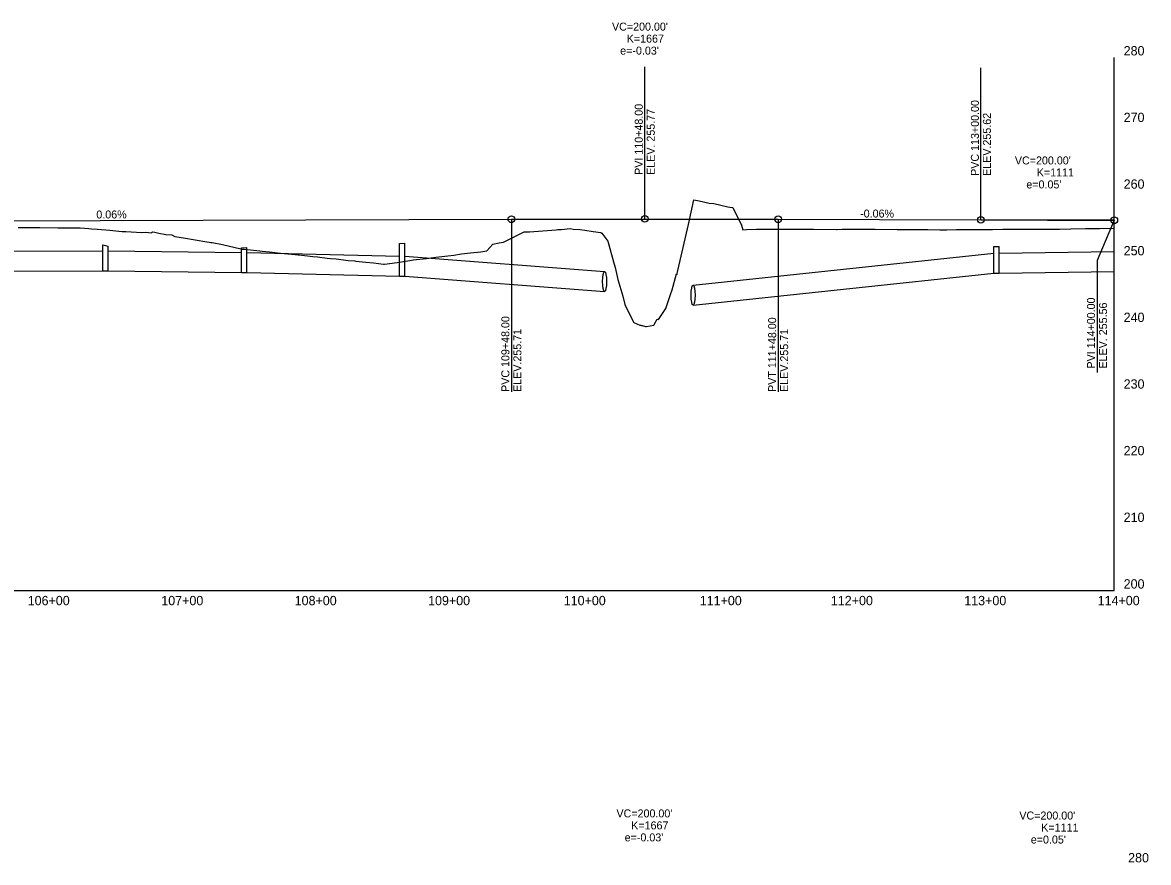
# Model space of a CAD drawing. Extents: x 1930770 to 1938778, y 596900 to 600561.
# Drawn here: x 1932838 to 1933682, y 599461 to 600091 of the extents above; entities that cross this region are included whole.
import ezdxf

# ---------------------------------------------------------------- set-up
doc = ezdxf.new("R2010")
doc.units = 0
for name, color, linetype in [('S_CROSS_DRAIN_ANNOT', 7, 'Continuous'), ('S_DROP_INLET_ANNOT', 7, 'Continuous'), ('S_ELECTRIC_UTILITIES_ANNOT', 7, 'Continuous'), ('S_HIST_HIGH_WATER_ANNOT', 7, 'Continuous'), ('S_SIGN_ANNOT', 7, 'Continuous'), ('S_WATER_UTILITIES_ANNOT', 7, 'Continuous')]:
    doc.layers.add(name, color=color, linetype=linetype)

msp = doc.modelspace()

# ---------------------------------------------------------------- linework, layer by layer
at = {"layer": 'S_CROSS_DRAIN_ANNOT'}
for p, q in [((1933656.02, 599664.63), (1933656.02, 600064.63)), ((1932156.02, 599664.63), (1933656.02, 599664.63))]:
    msp.add_line(p, q, dxfattribs=at)
at = {"layer": 'S_ELECTRIC_UTILITIES_ANNOT'}
for p, q in [((1933304.02, 599973.5), (1933304.02, 600057.5)), ((1933556.02, 599972.75), (1933556.02, 600056.75)), ((1933304.02, 599943.5), (1933304.02, 599973.5)), ((1933556.02, 599942.75), (1933556.02, 599972.75)), ((1933204.02, 599943.2), (1933204.02, 599913.2)), ((1933254.02, 599943.35), (1933304.02, 599943.5)), ((1933304.02, 599943.5), (1933354.02, 599943.35)), ((1933404.02, 599943.2), (1933404.02, 599913.2)), ((1933606.02, 599942.6), (1933656.02, 599942.45)), ((1933656.02, 599942.45), (1933643.04, 599912.19)), ((1933656.02, 599942.45), (1933656.02, 599942.45)), ((1933204.02, 599913.2), (1933204.02, 599813.65)), ((1933404.02, 599913.2), (1933404.02, 599813.65)), ((1933643.04, 599912.19), (1933643.04, 599828.19))]:
    msp.add_line(p, q, dxfattribs=at)
for centre in [(1933204.02, 599943.2), (1933304.02, 599943.5), (1933404.02, 599943.2), (1933556.02, 599942.75), (1933656.02, 599942.45)]:
    msp.add_circle(centre, 2.5, dxfattribs=at)
at = {"layer": 'S_HIST_HIGH_WATER_ANNOT'}
for p, q in [((1932606.02, 599941.41), (1933204.02, 599943.2)), ((1933404.02, 599943.2), (1933556.02, 599942.75))]:
    msp.add_line(p, q, dxfattribs=at)
for points in [[(1933204.02, 599943.2), (1933208.19, 599943.21), (1933212.36, 599943.23), (1933216.52, 599943.24), (1933220.69, 599943.25), (1933224.86, 599943.26), (1933229.02, 599943.27), (1933233.19, 599943.28), (1933237.36, 599943.29), (1933241.52, 599943.29), (1933245.69, 599943.3), (1933249.86, 599943.31), (1933254.02, 599943.32), (1933258.19, 599943.32), (1933262.36, 599943.33), (1933266.52, 599943.33), (1933270.69, 599943.34), (1933274.86, 599943.34), (1933279.02, 599943.34), (1933283.19, 599943.35), (1933287.36, 599943.35), (1933291.52, 599943.35), (1933295.69, 599943.35), (1933299.86, 599943.35), (1933308.19, 599943.35), (1933312.36, 599943.35), (1933316.52, 599943.35), (1933320.69, 599943.35), (1933324.86, 599943.35), (1933329.02, 599943.34), (1933333.19, 599943.34), (1933337.36, 599943.34), (1933341.52, 599943.33), (1933345.69, 599943.33), (1933349.86, 599943.32), (1933354.02, 599943.32), (1933358.19, 599943.31), (1933362.36, 599943.3), (1933366.52, 599943.29), (1933370.69, 599943.29), (1933374.86, 599943.28), (1933379.02, 599943.27), (1933383.19, 599943.26), (1933387.36, 599943.25), (1933391.52, 599943.24), (1933395.69, 599943.23), (1933399.86, 599943.21), (1933404.02, 599943.2)], [(1933556.02, 599942.75), (1933560.19, 599942.73), (1933564.36, 599942.72), (1933568.52, 599942.71), (1933572.69, 599942.7), (1933576.86, 599942.69), (1933581.02, 599942.69), (1933585.19, 599942.68), (1933589.36, 599942.67), (1933593.52, 599942.67), (1933597.69, 599942.66), (1933601.86, 599942.66), (1933606.02, 599942.65), (1933610.19, 599942.65), (1933614.36, 599942.65), (1933618.52, 599942.65), (1933622.69, 599942.65), (1933626.86, 599942.65), (1933631.02, 599942.65), (1933635.19, 599942.65), (1933639.36, 599942.65), (1933643.52, 599942.66), (1933647.69, 599942.66), (1933651.86, 599942.67), (1933656.02, 599942.67)]]:
    msp.add_lwpolyline(points, dxfattribs=at)
at = {"layer": 'S_SIGN_ANNOT'}
for p, q in [((1932897.73, 599904.58), (1932897.73, 599924.05)), ((1932897.73, 599924.05), (1932901.73, 599923.09)), ((1932901.73, 599904.58), (1932901.73, 599923.09)), ((1933001.63, 599921.87), (1933005.63, 599921.91)), ((1933001.63, 599903.23), (1933001.63, 599921.87)), ((1933005.63, 599903.23), (1933005.63, 599921.91)), ((1933120.14, 599924.93), (1933124.14, 599925.24)), ((1933120.14, 599900.43), (1933120.14, 599924.93)), ((1933124.14, 599900.43), (1933124.14, 599925.24)), ((1933565.71, 599902.73), (1933565.71, 599922.86)), ((1933565.71, 599922.86), (1933569.71, 599922.83)), ((1933569.71, 599902.73), (1933569.71, 599922.83)), ((1932819.18, 599919.33), (1932897.73, 599919.58)), ((1932901.73, 599919.58), (1933001.63, 599918.23)), ((1933005.63, 599918.23), (1933120.14, 599915.43)), ((1933124.14, 599915.43), (1933273.9, 599903.98)), ((1933340.26, 599893.78), (1933565.71, 599917.73)), ((1933569.71, 599917.73), (1933656.02, 599918.98)), ((1932819.18, 599904.33), (1932897.73, 599904.58)), ((1932897.73, 599904.58), (1932901.73, 599904.58)), ((1932901.73, 599904.58), (1933001.63, 599903.23)), ((1933001.63, 599903.23), (1933005.63, 599903.23)), ((1933005.63, 599903.23), (1933120.14, 599900.43)), ((1933569.71, 599902.73), (1933656.02, 599903.98)), ((1933120.14, 599900.43), (1933124.14, 599900.43)), ((1933124.14, 599900.43), (1933273.9, 599888.98)), ((1933340.26, 599878.78), (1933565.71, 599902.73)), ((1933565.71, 599902.73), (1933569.71, 599902.73))]:
    msp.add_line(p, q, dxfattribs=at)
for centre in [(1933273.9, 599896.48), (1933340.26, 599886.28)]:
    msp.add_ellipse(centre, major_axis=(0, 7.5), ratio=0.2, dxfattribs=at)
at = {"layer": 'S_WATER_UTILITIES_ANNOT'}
msp.add_lwpolyline([(1932834.28, 599937.02), (1932843.89, 599936.98), (1932850.52, 599936.93), (1932863.99, 599936.81), (1932867.66, 599936.8), (1932872.05, 599936.77), (1932880.8, 599936.73), (1932887.28, 599936.22), (1932889.22, 599936.06), (1932893.59, 599935.7), (1932893.86, 599935.68), (1932903.14, 599934.91), (1932909.83, 599934.32), (1932912.23, 599934.09), (1932915.12, 599933.95), (1932926.9, 599933.35), (1932929.71, 599933.61), (1932934.33, 599932.95), (1932935.11, 599933.75), (1932936.66, 599933.42), (1932939.78, 599932.74), (1932945.12, 599931.65), (1932949.46, 599931.47), (1932951.86, 599930.28), (1932956.39, 599929.63), (1932958.19, 599929.32), (1932975.74, 599926.29), (1932977.45, 599926.03), (1932978.67, 599925.84), (1932979.72, 599925.65), (1932987.47, 599924.24), (1933001.26, 599921.01), (1933002.12, 599920.8), (1933003.64, 599920.68), (1933015.41, 599919.43), (1933017.32, 599919.28), (1933022.79, 599918.71), (1933028.7, 599918.05), (1933031.05, 599917.85), (1933041.98, 599916.65), (1933044.32, 599916.46), (1933044.83, 599916.41), (1933055.26, 599915.21), (1933058.7, 599914.92), (1933065.86, 599914.11), (1933068.52, 599913.79), (1933072.62, 599913.42), (1933081.78, 599912.34), (1933086.62, 599911.92), (1933087.39, 599911.83), (1933095.02, 599910.9), (1933100.72, 599910.4), (1933108.26, 599909.49), (1933108.92, 599909.57), (1933118.34, 599910.64), (1933127.97, 599912.36), (1933130.46, 599912.64), (1933140.37, 599913.73), (1933147.33, 599914.85), (1933151.99, 599915.37), (1933160.99, 599916.36), (1933166.53, 599917.21), (1933173.42, 599917.97), (1933181.02, 599918.84), (1933185.63, 599919.54), (1933190.13, 599924.55), (1933194.84, 599925.4), (1933198.25, 599926.01), (1933202.24, 599927.93), (1933213.64, 599933.74), (1933214.49, 599933.82), (1933216.27, 599933.75), (1933217.72, 599933.7), (1933237.7, 599935.3), (1933238.92, 599935.4), (1933241.7, 599935.58), (1933248.03, 599936.31), (1933250.24, 599935.83), (1933255.33, 599935.44), (1933259.12, 599934.9), (1933265.45, 599934.01), (1933271.17, 599933.23), (1933271.87, 599932.71), (1933276.32, 599926.87), (1933280.55, 599911.31), (1933281.75, 599906.9), (1933283.85, 599898.11), (1933287.49, 599885.61), (1933289.14, 599879.29), (1933294.17, 599869.1), (1933295.78, 599865.64), (1933300.45, 599863.83), (1933301.1, 599863.66), (1933301.62, 599863.53), (1933301.98, 599863.44), (1933304.66, 599862.76), (1933305.36, 599862.66), (1933310.71, 599863.64), (1933310.99, 599864.31), (1933313.36, 599868.29), (1933314.35, 599868.05), (1933319.84, 599876.13), (1933323.4, 599886.75), (1933324.59, 599890.28), (1933327.91, 599902.18), (1933328.01, 599901.56), (1933336.79, 599939.16), (1933340.91, 599957.82), (1933344.83, 599956.96), (1933352.28, 599955.33), (1933355.74, 599954.93), (1933366.26, 599952.54), (1933367.84, 599952.18), (1933370.15, 599951.91), (1933376.57, 599938.81), (1933377.55, 599935.38), (1933380.24, 599935.63), (1933387.68, 599935.69), (1933398.51, 599935.78), (1933401.03, 599935.8), (1933409.11, 599935.77), (1933421.84, 599935.71), (1933423.34, 599935.72), (1933424.68, 599935.73), (1933430.54, 599935.7), (1933447.82, 599935.6), (1933447.99, 599935.6), (1933448.18, 599935.61), (1933451.96, 599935.67), (1933452.99, 599935.69), (1933458.38, 599935.78), (1933458.64, 599935.77), (1933473.39, 599935.68), (1933475.63, 599935.67), (1933476.84, 599935.67), (1933493.26, 599935.57), (1933494.82, 599935.57), (1933495.89, 599935.57), (1933511.33, 599935.48), (1933516.24, 599935.45), (1933525.33, 599935.39), (1933530.48, 599935.38), (1933537.67, 599935.47), (1933546.01, 599935.57), (1933553.49, 599935.46), (1933559.09, 599935.55), (1933564.58, 599935.63), (1933572.35, 599935.75), (1933580.52, 599935.84), (1933585.81, 599935.89), (1933592.36, 599935.89), (1933592.82, 599935.89), (1933601.95, 599935.89), (1933613.32, 599935.88), (1933615.04, 599935.86), (1933623.37, 599936.01), (1933634.46, 599936.21), (1933636.69, 599936.19), (1933644.8, 599936.33), (1933655.57, 599936.52), (1933656.02, 599936.51)], dxfattribs=at)

# ---------------------------------------------------------------- texts
at = {"layer": 'S_DROP_INLET_ANNOT'}
for s, p in [('280', (1933663.02, 600066.13)), ('280', (1933663.02, 600066.13)), ('270', (1933663.02, 600016.13)), ('260', (1933663.02, 599966.13)), ('250', (1933663.02, 599916.13)), ('240', (1933663.02, 599866.13)), ('230', (1933663.02, 599816.13)), ('220', (1933663.02, 599766.13)), ('210', (1933663.02, 599716.13)), ('200', (1933663.02, 599666.13)), ('106+00', (1932841.45, 599653.63)), ('107+00', (1932941.59, 599653.63)), ('108+00', (1933041.59, 599653.63)), ('109+00', (1933141.59, 599653.63)), ('110+00', (1933243.29, 599653.63)), ('111+00', (1933345.23, 599653.63)), ('112+00', (1933443.53, 599653.63)), ('113+00', (1933543.53, 599653.63)), ('114+00', (1933643.53, 599653.63)), ('280', (1933666.37, 599460.71)), ('280', (1933666.37, 599460.71))]:
    msp.add_text(s, height=7, dxfattribs=at).set_placement(p)
at = {"layer": 'S_ELECTRIC_UTILITIES_ANNOT'}
for s, p in [("VC=200.00'", (1933279.46, 600084.73)), ('K=1667', (1933290.51, 600075.73)), ("e=-0.03'", (1933285.6, 600066.73)), ("VC=200.00'", (1933581.46, 599984.34)), ('K=1111', (1933597.9, 599975.34)), ("e=0.05'", (1933590.06, 599966.34)), ("VC=200.00'", (1933282.8, 599494.45)), ("VC=200.00'", (1933584.8, 599492.85)), ('K=1667', (1933293.86, 599485.45)), ('K=1111', (1933601.25, 599483.85)), ("e=-0.03'", (1933288.95, 599476.45)), ("e=0.05'", (1933593.4, 599474.85))]:
    msp.add_text(s, height=6, dxfattribs=at).set_placement(p)
for s, rotation, p in [('PVI 110+48.00', 90, (1933302.52, 599976.5)), ('PVC 113+00.00', 90, (1933554.52, 599975.75)), ('ELEV. 255.77', 90, (1933311.52, 599976.5)), ('ELEV.255.62', 90, (1933563.52, 599975.75)), ('0.06%', 0.17189, (1932892.9, 599943.77)), ('-0.06%', 359.82811, (1933465.45, 599944.52)), ('PVI 114+00.00', 90, (1933641.54, 599831.19)), ('ELEV. 255.56', 90, (1933650.54, 599831.19)), ('PVC 109+48.00', 90, (1933202.52, 599813.65)), ('PVT 111+48.00', 90, (1933402.52, 599813.65)), ('ELEV.255.71', 90, (1933211.52, 599813.65)), ('ELEV.255.71', 90, (1933411.52, 599813.65))]:
    msp.add_text(s, height=6, rotation=rotation, dxfattribs=at).set_placement(p)

doc.saveas('drawing.dxf')
